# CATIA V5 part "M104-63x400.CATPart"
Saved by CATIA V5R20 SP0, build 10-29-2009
Part number: M104-63x400
Source: Unknown
Bounding box of the stored display mesh (mm): x -31.459 to 31.459, y -31.459 to 31.459, z 0 to 400
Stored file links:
  C:\Users\Utente\Desktop\IO LAVORO\3D X SITO CF\X SITO\M104\M104-63x400.CATPart
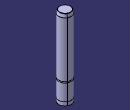
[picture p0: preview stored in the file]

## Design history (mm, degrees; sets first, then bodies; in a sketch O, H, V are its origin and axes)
Body1 (main body)
  Solid1 "PartBody": solid without history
